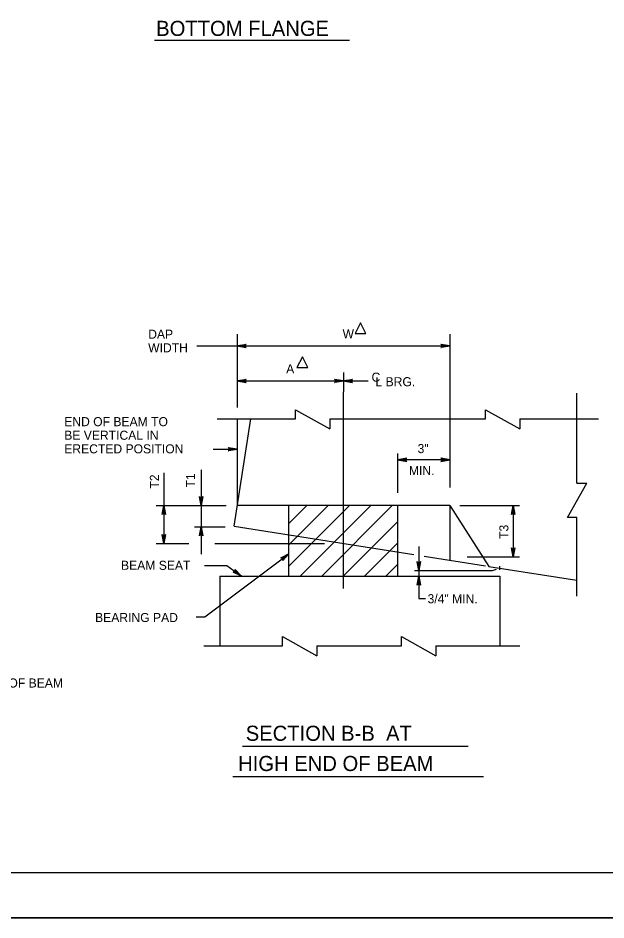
# Model space of a CAD drawing. Extents: x 637933 to 640019, y 298854 to 300042.
# Drawn here: x 639207 to 639401.6, y 299447.5 to 299746 of the extents above; entities that cross this region are included whole.
import ezdxf

# ---------------------------------------------------------------- set-up
doc = ezdxf.new("R2010")
doc.units = 0
doc.layers.add('1', color=7, linetype='Continuous')
doc.layers.add('PLT-BNDY', color=7, linetype='Continuous')

msp = doc.modelspace()

# ---------------------------------------------------------------- linework, layer by layer
at = {"layer": '1'}
for p, q in [((639279.6, 299641.33), (639279.6, 299617.08)), ((639349.95, 299641.33), (639349.95, 299590.59)), ((639266.2, 299637.46), (639349.95, 299637.46)), ((639314.78, 299628.61), (639314.78, 299622.24)), ((639279.6, 299625.86), (639314.78, 299625.86)), ((639314.78, 299625.86), (639322.91, 299625.86)), ((639314.78, 299557.17), (639314.78, 299622.24)), ((639391.98, 299592.01), (639391.98, 299621.81)), ((639298.9, 299613.28), (639298.9, 299616.33)), ((639298.9, 299616.33), (639310.25, 299610.02)), ((639361.74, 299613.28), (639361.74, 299616.33)), ((639361.74, 299616.33), (639373.09, 299610.02)), ((639272.9, 299613.28), (639298.9, 299613.28)), ((639278.53, 299577.79), (639284.12, 299613.28)), ((639279.6, 299613.28), (639279.6, 299584.59)), ((639310.25, 299613.28), (639361.74, 299613.28)), ((639310.25, 299613.28), (639310.25, 299610.02)), ((639373.09, 299613.28), (639373.09, 299610.02)), ((639373.09, 299613.28), (639399.09, 299613.28)), ((639271.59, 299603.24), (639279.6, 299603.24)), ((639332.68, 299588.84), (639332.68, 299601.86)), ((639349.95, 299599.8), (639332.68, 299599.8)), ((639255.27, 299595.48), (639255.27, 299584.59)), ((639267.62, 299596.42), (639267.62, 299584.59)), ((639388.92, 299580.65), (639395.23, 299592.01)), ((639391.98, 299592.01), (639395.23, 299592.01)), ((639252.73, 299584.59), (639275.94, 299584.59)), ((639255.27, 299584.59), (639255.27, 299572.08)), ((639267.62, 299584.59), (639267.62, 299577.62)), ((639349.95, 299584.59), (639279.6, 299584.59)), ((639296.68, 299561.25), (639296.68, 299584.59)), ((639296.68, 299578.69), (639302.59, 299584.59)), ((639296.68, 299571.62), (639309.66, 299584.59)), ((639296.68, 299564.55), (639316.73, 299584.59)), ((639300.46, 299561.25), (639323.8, 299584.59)), ((639307.53, 299561.25), (639330.87, 299584.59)), ((639332.68, 299561.25), (639332.68, 299584.59)), ((639349.95, 299584.59), (639362.84, 299564.5)), ((639349.95, 299584.59), (639349.95, 299566.53)), ((639353.21, 299584.59), (639373.04, 299584.59)), ((639370.91, 299584.59), (639370.91, 299567.67)), ((639391.98, 299580.65), (639388.92, 299580.65)), ((639391.98, 299554.65), (639391.98, 299580.65)), ((639265.46, 299577.62), (639275.62, 299577.62)), ((639267.62, 299577.62), (639267.62, 299568.55)), ((639278.53, 299577.79), (639338, 299568.42)), ((639314.6, 299561.25), (639332.68, 299579.33)), ((639252.73, 299572.08), (639263.58, 299572.08)), ((639272.19, 299572.08), (639308.51, 299572.08)), ((639321.67, 299561.25), (639332.68, 299572.26)), ((639339.64, 299571.06), (639339.64, 299564.5)), ((639268.91, 299547.81), (639296.68, 299568.67)), ((639341.44, 299567.87), (639361.77, 299564.67)), ((639355.7, 299567.67), (639373.04, 299567.67)), ((639268.8, 299564.75), (639276.16, 299564.75)), ((639276.16, 299564.75), (639280.99, 299561.25)), ((639328.74, 299561.25), (639332.68, 299565.19)), ((639339.64, 299564.5), (639339.64, 299561.25)), ((639362.84, 299564.5), (639391.98, 299559.91)), ((639366.47, 299563.35), (639366.47, 299564.61)), ((639338.24, 299563.08), (639364.07, 299563.08)), ((639364.07, 299563.08), (639365.4, 299563.55)), ((639273.83, 299561.25), (639273.83, 299538.18)), ((639273.83, 299561.25), (639366.47, 299561.25)), ((639339.64, 299561.25), (639339.64, 299553.83)), ((639366.47, 299561.25), (639366.47, 299538.18)), ((639339.64, 299553.83), (639341.86, 299553.83)), ((639265.95, 299547.81), (639268.91, 299547.81)), ((639294.54, 299538.18), (639294.54, 299541.24)), ((639294.54, 299541.24), (639305.9, 299534.93)), ((639333.92, 299538.18), (639333.92, 299541.24)), ((639333.92, 299541.24), (639345.27, 299534.93)), ((639268.54, 299538.18), (639294.54, 299538.18)), ((639305.9, 299538.18), (639333.92, 299538.18)), ((639305.9, 299538.18), (639305.9, 299534.93)), ((639345.27, 299538.18), (639345.27, 299534.93)), ((639345.27, 299538.18), (639373.13, 299538.18)), ((639356.05, 299504.86), (639281.3, 299504.86)), ((639361.08, 299494.82), (639278.08, 299494.82)), ((639650.94, 299463.12), (638864.93, 299463.12))]:
    msp.add_line(p, q, dxfattribs=at)
for points in [[(639252.2, 299738.69), (639316.7, 299738.69)], [(639279.6, 299637.46), (639282.58, 299638.02), (639282.47, 299637.94), (639282.35, 299637.86), (639282.3, 299637.76), (639282.24, 299637.66), (639282.22, 299637.56), (639282.2, 299637.46), (639282.22, 299637.36), (639282.24, 299637.26), (639282.3, 299637.16), (639282.35, 299637.06), (639282.47, 299636.98), (639282.58, 299636.9), (639279.6, 299637.46), (639282.47, 299636.98), (639282.35, 299637.06), (639279.6, 299637.46), (639282.3, 299637.16), (639282.24, 299637.26), (639279.6, 299637.46), (639282.22, 299637.36), (639282.2, 299637.46), (639279.6, 299637.46), (639282.22, 299637.56), (639282.24, 299637.66), (639279.6, 299637.46), (639282.3, 299637.76), (639282.35, 299637.86), (639279.6, 299637.46), (639282.47, 299637.94)], [(639349.95, 299637.46), (639346.97, 299636.9), (639347.08, 299636.98), (639347.2, 299637.06), (639347.26, 299637.16), (639347.32, 299637.26), (639347.34, 299637.36), (639347.35, 299637.46), (639347.34, 299637.56), (639347.32, 299637.66), (639347.26, 299637.76), (639347.2, 299637.86), (639347.08, 299637.94), (639346.97, 299638.02), (639349.95, 299637.46), (639347.08, 299637.94), (639347.2, 299637.86), (639349.95, 299637.46), (639347.26, 299637.76), (639347.32, 299637.66), (639349.95, 299637.46), (639347.34, 299637.56), (639347.35, 299637.46), (639349.95, 299637.46), (639347.34, 299637.36), (639347.32, 299637.26), (639349.95, 299637.46), (639347.26, 299637.16), (639347.2, 299637.06), (639349.95, 299637.46), (639347.08, 299636.98)], [(639279.6, 299625.86), (639282.58, 299626.42), (639282.47, 299626.34), (639282.35, 299626.26), (639282.3, 299626.16), (639282.24, 299626.06), (639282.22, 299625.96), (639282.2, 299625.86), (639282.22, 299625.76), (639282.24, 299625.66), (639282.3, 299625.56), (639282.35, 299625.46), (639282.47, 299625.38), (639282.58, 299625.3), (639279.6, 299625.86), (639282.47, 299625.38), (639282.35, 299625.46), (639279.6, 299625.86), (639282.3, 299625.56), (639282.24, 299625.66), (639279.6, 299625.86), (639282.22, 299625.76), (639282.2, 299625.86), (639279.6, 299625.86), (639282.22, 299625.96), (639282.24, 299626.06), (639279.6, 299625.86), (639282.3, 299626.16), (639282.35, 299626.26), (639279.6, 299625.86), (639282.47, 299626.34)], [(639314.78, 299625.86), (639311.79, 299625.3), (639311.91, 299625.38), (639312.02, 299625.46), (639312.08, 299625.56), (639312.14, 299625.66), (639312.16, 299625.76), (639312.18, 299625.86), (639312.16, 299625.96), (639312.14, 299626.06), (639312.08, 299626.16), (639312.02, 299626.26), (639311.91, 299626.34), (639311.79, 299626.42), (639314.78, 299625.86), (639311.91, 299626.34), (639312.02, 299626.26), (639314.78, 299625.86), (639312.08, 299626.16), (639312.14, 299626.06), (639314.78, 299625.86), (639312.16, 299625.96), (639312.18, 299625.86), (639314.78, 299625.86), (639312.16, 299625.76), (639312.14, 299625.66), (639314.78, 299625.86), (639312.08, 299625.56), (639312.02, 299625.46), (639314.78, 299625.86), (639311.91, 299625.38)], [(639314.78, 299625.86), (639317.76, 299626.42), (639317.65, 299626.34), (639317.53, 299626.26), (639317.47, 299626.16), (639317.41, 299626.06), (639317.39, 299625.96), (639317.38, 299625.86), (639317.39, 299625.76), (639317.41, 299625.66), (639317.47, 299625.56), (639317.53, 299625.46), (639317.65, 299625.38), (639317.76, 299625.3), (639314.78, 299625.86), (639317.65, 299625.38), (639317.53, 299625.46), (639314.78, 299625.86), (639317.47, 299625.56), (639317.41, 299625.66), (639314.78, 299625.86), (639317.39, 299625.76), (639317.38, 299625.86), (639314.78, 299625.86), (639317.39, 299625.96), (639317.41, 299626.06), (639314.78, 299625.86), (639317.47, 299626.16), (639317.53, 299626.26), (639314.78, 299625.86), (639317.65, 299626.34)], [(639279.6, 299603.24), (639276.62, 299602.68), (639276.73, 299602.76), (639276.85, 299602.84), (639276.91, 299602.94), (639276.97, 299603.04), (639276.98, 299603.14), (639277, 299603.24), (639276.98, 299603.34), (639276.97, 299603.44), (639276.91, 299603.54), (639276.85, 299603.64), (639276.73, 299603.72), (639276.62, 299603.8), (639279.6, 299603.24), (639276.73, 299603.72), (639276.85, 299603.64), (639279.6, 299603.24), (639276.91, 299603.54), (639276.97, 299603.44), (639279.6, 299603.24), (639276.98, 299603.34), (639277, 299603.24), (639279.6, 299603.24), (639276.98, 299603.14), (639276.97, 299603.04), (639279.6, 299603.24), (639276.91, 299602.94), (639276.85, 299602.84), (639279.6, 299603.24), (639276.73, 299602.76)], [(639332.68, 299599.8), (639335.67, 299599.24), (639335.55, 299599.32), (639335.44, 299599.4), (639335.38, 299599.5), (639335.32, 299599.6), (639335.3, 299599.7), (639335.28, 299599.8), (639335.3, 299599.9), (639335.32, 299600), (639335.38, 299600.1), (639335.44, 299600.2), (639335.55, 299600.28), (639335.67, 299600.36), (639332.68, 299599.8), (639335.55, 299600.28), (639335.44, 299600.2), (639332.68, 299599.8), (639335.38, 299600.1), (639335.32, 299600), (639332.68, 299599.8), (639335.3, 299599.9), (639335.28, 299599.8), (639332.68, 299599.8), (639335.3, 299599.7), (639335.32, 299599.6), (639332.68, 299599.8), (639335.38, 299599.5), (639335.44, 299599.4), (639332.68, 299599.8), (639335.55, 299599.32)], [(639349.95, 299599.8), (639346.97, 299600.36), (639347.08, 299600.28), (639347.2, 299600.2), (639347.26, 299600.1), (639347.32, 299600), (639347.34, 299599.9), (639347.35, 299599.8), (639347.34, 299599.7), (639347.32, 299599.6), (639347.26, 299599.5), (639347.2, 299599.4), (639347.08, 299599.32), (639346.97, 299599.24), (639349.95, 299599.8), (639347.08, 299599.32), (639347.2, 299599.4), (639349.95, 299599.8), (639347.26, 299599.5), (639347.32, 299599.6), (639349.95, 299599.8), (639347.34, 299599.7), (639347.35, 299599.8), (639349.95, 299599.8), (639347.34, 299599.9), (639347.32, 299600), (639349.95, 299599.8), (639347.26, 299600.1), (639347.2, 299600.2), (639349.95, 299599.8), (639347.08, 299600.28)], [(639267.62, 299584.59), (639267.06, 299587.57), (639267.14, 299587.46), (639267.22, 299587.34), (639267.32, 299587.28), (639267.42, 299587.22), (639267.52, 299587.21), (639267.62, 299587.19), (639267.72, 299587.21), (639267.82, 299587.22), (639267.92, 299587.28), (639268.02, 299587.34), (639268.1, 299587.46), (639268.18, 299587.57), (639267.62, 299584.59), (639268.1, 299587.46), (639268.02, 299587.34), (639267.62, 299584.59), (639267.92, 299587.28), (639267.82, 299587.22), (639267.62, 299584.59), (639267.72, 299587.21), (639267.62, 299587.19), (639267.62, 299584.59), (639267.52, 299587.21), (639267.42, 299587.22), (639267.62, 299584.59), (639267.32, 299587.28), (639267.22, 299587.34), (639267.62, 299584.59), (639267.14, 299587.46)], [(639255.27, 299584.59), (639255.83, 299581.61), (639255.75, 299581.72), (639255.67, 299581.84), (639255.57, 299581.89), (639255.47, 299581.95), (639255.37, 299581.97), (639255.27, 299581.99), (639255.17, 299581.97), (639255.07, 299581.95), (639254.97, 299581.89), (639254.87, 299581.84), (639254.79, 299581.72), (639254.71, 299581.61), (639255.27, 299584.59), (639254.79, 299581.72), (639254.87, 299581.84), (639255.27, 299584.59), (639254.97, 299581.89), (639255.07, 299581.95), (639255.27, 299584.59), (639255.17, 299581.97), (639255.27, 299581.99), (639255.27, 299584.59), (639255.37, 299581.97), (639255.47, 299581.95), (639255.27, 299584.59), (639255.57, 299581.89), (639255.67, 299581.84), (639255.27, 299584.59), (639255.75, 299581.72)], [(639370.91, 299584.59), (639371.47, 299581.61), (639371.39, 299581.72), (639371.31, 299581.84), (639371.21, 299581.89), (639371.11, 299581.95), (639371.01, 299581.97), (639370.91, 299581.99), (639370.81, 299581.97), (639370.71, 299581.95), (639370.61, 299581.89), (639370.51, 299581.84), (639370.43, 299581.72), (639370.35, 299581.61), (639370.91, 299584.59), (639370.43, 299581.72), (639370.51, 299581.84), (639370.91, 299584.59), (639370.61, 299581.89), (639370.71, 299581.95), (639370.91, 299584.59), (639370.81, 299581.97), (639370.91, 299581.99), (639370.91, 299584.59), (639371.01, 299581.97), (639371.11, 299581.95), (639370.91, 299584.59), (639371.21, 299581.89), (639371.31, 299581.84), (639370.91, 299584.59), (639371.39, 299581.72)], [(639267.62, 299577.62), (639268.18, 299574.64), (639268.1, 299574.75), (639268.02, 299574.87), (639267.92, 299574.93), (639267.82, 299574.99), (639267.72, 299575), (639267.62, 299575.02), (639267.52, 299575), (639267.42, 299574.99), (639267.32, 299574.93), (639267.22, 299574.87), (639267.14, 299574.75), (639267.06, 299574.64), (639267.62, 299577.62), (639267.14, 299574.75), (639267.22, 299574.87), (639267.62, 299577.62), (639267.32, 299574.93), (639267.42, 299574.99), (639267.62, 299577.62), (639267.52, 299575), (639267.62, 299575.02), (639267.62, 299577.62), (639267.72, 299575), (639267.82, 299574.99), (639267.62, 299577.62), (639267.92, 299574.93), (639268.02, 299574.87), (639267.62, 299577.62), (639268.1, 299574.75)], [(639255.27, 299572.08), (639254.71, 299575.06), (639254.79, 299574.94), (639254.87, 299574.83), (639254.97, 299574.77), (639255.07, 299574.71), (639255.17, 299574.69), (639255.27, 299574.68), (639255.37, 299574.69), (639255.47, 299574.71), (639255.57, 299574.77), (639255.67, 299574.83), (639255.75, 299574.94), (639255.83, 299575.06), (639255.27, 299572.08), (639255.75, 299574.94), (639255.67, 299574.83), (639255.27, 299572.08), (639255.57, 299574.77), (639255.47, 299574.71), (639255.27, 299572.08), (639255.37, 299574.69), (639255.27, 299574.68), (639255.27, 299572.08), (639255.17, 299574.69), (639255.07, 299574.71), (639255.27, 299572.08), (639254.97, 299574.77), (639254.87, 299574.83), (639255.27, 299572.08), (639254.79, 299574.94)], [(639370.91, 299567.67), (639370.35, 299570.65), (639370.43, 299570.54), (639370.51, 299570.42), (639370.61, 299570.36), (639370.71, 299570.3), (639370.81, 299570.29), (639370.91, 299570.27), (639371.01, 299570.29), (639371.11, 299570.3), (639371.21, 299570.36), (639371.31, 299570.42), (639371.39, 299570.54), (639371.47, 299570.65), (639370.91, 299567.67), (639371.39, 299570.54), (639371.31, 299570.42), (639370.91, 299567.67), (639371.21, 299570.36), (639371.11, 299570.3), (639370.91, 299567.67), (639371.01, 299570.29), (639370.91, 299570.27), (639370.91, 299567.67), (639370.81, 299570.29), (639370.71, 299570.3), (639370.91, 299567.67), (639370.61, 299570.36), (639370.51, 299570.42), (639370.91, 299567.67), (639370.43, 299570.54)], [(639296.68, 299568.67), (639294.63, 299566.43), (639294.68, 299566.57), (639294.72, 299566.7), (639294.71, 299566.81), (639294.7, 299566.93), (639294.65, 299567.02), (639294.6, 299567.11), (639294.53, 299567.18), (639294.46, 299567.25), (639294.35, 299567.29), (639294.24, 299567.34), (639294.1, 299567.33), (639293.96, 299567.33), (639296.68, 299568.67), (639294.1, 299567.33), (639294.24, 299567.34), (639296.68, 299568.67), (639294.35, 299567.29), (639294.46, 299567.25), (639296.68, 299568.67), (639294.53, 299567.18), (639294.6, 299567.11), (639296.68, 299568.67), (639294.65, 299567.02), (639294.7, 299566.93), (639296.68, 299568.67), (639294.71, 299566.81), (639294.72, 299566.7), (639296.68, 299568.67), (639294.68, 299566.57)], [(639339.64, 299563.08), (639339.08, 299566.06), (639339.16, 299565.95), (639339.24, 299565.83), (639339.34, 299565.77), (639339.44, 299565.71), (639339.54, 299565.69), (639339.64, 299565.68), (639339.74, 299565.69), (639339.84, 299565.71), (639339.94, 299565.77), (639340.04, 299565.83), (639340.12, 299565.95), (639340.2, 299566.06), (639339.64, 299563.08), (639340.12, 299565.95), (639340.04, 299565.83), (639339.64, 299563.08), (639339.94, 299565.77), (639339.84, 299565.71), (639339.64, 299563.08), (639339.74, 299565.69), (639339.64, 299565.68), (639339.64, 299563.08), (639339.54, 299565.69), (639339.44, 299565.71), (639339.64, 299563.08), (639339.34, 299565.77), (639339.24, 299565.83), (639339.64, 299563.08), (639339.16, 299565.95)], [(639280.99, 299561.25), (639278.25, 299562.54), (639278.39, 299562.54), (639278.53, 299562.54), (639278.64, 299562.58), (639278.74, 299562.63), (639278.82, 299562.7), (639278.89, 299562.77), (639278.93, 299562.86), (639278.98, 299562.95), (639278.99, 299563.07), (639279, 299563.19), (639278.95, 299563.32), (639278.91, 299563.45), (639280.99, 299561.25), (639278.95, 299563.32), (639279, 299563.19), (639280.99, 299561.25), (639278.99, 299563.07), (639278.98, 299562.95), (639280.99, 299561.25), (639278.93, 299562.86), (639278.89, 299562.77), (639280.99, 299561.25), (639278.82, 299562.7), (639278.74, 299562.63), (639280.99, 299561.25), (639278.64, 299562.58), (639278.53, 299562.54), (639280.99, 299561.25), (639278.39, 299562.54)], [(639339.64, 299561.25), (639340.2, 299558.27), (639340.12, 299558.38), (639340.04, 299558.49), (639339.94, 299558.55), (639339.84, 299558.61), (639339.74, 299558.63), (639339.64, 299558.65), (639339.54, 299558.63), (639339.44, 299558.61), (639339.34, 299558.55), (639339.24, 299558.49), (639339.16, 299558.38), (639339.08, 299558.27), (639339.64, 299561.25), (639339.16, 299558.38), (639339.24, 299558.49), (639339.64, 299561.25), (639339.34, 299558.55), (639339.44, 299558.61), (639339.64, 299561.25), (639339.54, 299558.63), (639339.64, 299558.65), (639339.64, 299561.25), (639339.74, 299558.63), (639339.84, 299558.61), (639339.64, 299561.25), (639339.94, 299558.55), (639340.04, 299558.49), (639339.64, 299561.25), (639340.12, 299558.38)]]:
    msp.add_lwpolyline(points, dxfattribs=at)
for points in [[(639318.59, 299641.53), (639322.14, 299641.53), (639320.36, 299645.07)], [(639299.36, 299630.29), (639302.9, 299630.29), (639301.13, 299633.84)]]:
    msp.add_lwpolyline(points, close=True, dxfattribs=at)
at = {"layer": 'PLT-BNDY'}
for points in [[(638824.93, 300042.12), (639665.93, 300042.12), (639665.93, 299448.12), (638824.93, 299448.12)], [(638824.93, 299448.12), (639665.93, 299448.12), (639665.93, 298854.12), (638824.93, 298854.12)]]:
    msp.add_lwpolyline(points, close=True, dxfattribs=at)

# ---------------------------------------------------------------- texts
at = {"layer": '1'}
for s, height, p in [('BOTTOM FLANGE', 5, (639252.75, 299740.05)), ('DAP', 3, (639250.11, 299639.83)), ('W', 3, (639314.45, 299639.96)), ('WIDTH', 3, (639250.11, 299635.33)), ('A', 3, (639295.78, 299628.36)), ('C', 3, (639324.03, 299625.61)), ('L BRG.', 3, (639325.34, 299624.11)), ('END OF BEAM TO', 3, (639222.33, 299610.89)), ('BE VERTICAL IN', 3, (639222.33, 299606.39)), ('ERECTED POSITION', 3, (639222.33, 299601.89)), ('3"', 3, (639339.27, 299601.98)), ('MIN.', 3, (639336.4, 299594.68)), ('BEAM SEAT', 3, (639241.13, 299563.35)), ('3/4" MIN.', 3, (639342.57, 299552.28)), ('BEARING PAD', 3, (639232.54, 299546.07)), ('- MEASURED ALONG   OF BEAM', 3, (639160.17, 299524.4)), ('SECTION B-B  AT', 4.9998, (639282.4, 299506.76)), ('HIGH END OF BEAM', 4.9998, (639279.88, 299496.76))]:
    msp.add_text(s, height=height, dxfattribs=at).set_placement(p)
for s, p in [('T2', (639253.67, 299590.24)), ('T1', (639265.65, 299590.62)), ('T3', (639369.33, 299573.59))]:
    msp.add_text(s, height=3, rotation=90, dxfattribs=at).set_placement(p)

doc.saveas('drawing.dxf')
